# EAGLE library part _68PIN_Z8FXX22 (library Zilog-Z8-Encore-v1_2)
Z8 Encore, PLCC-68 Package
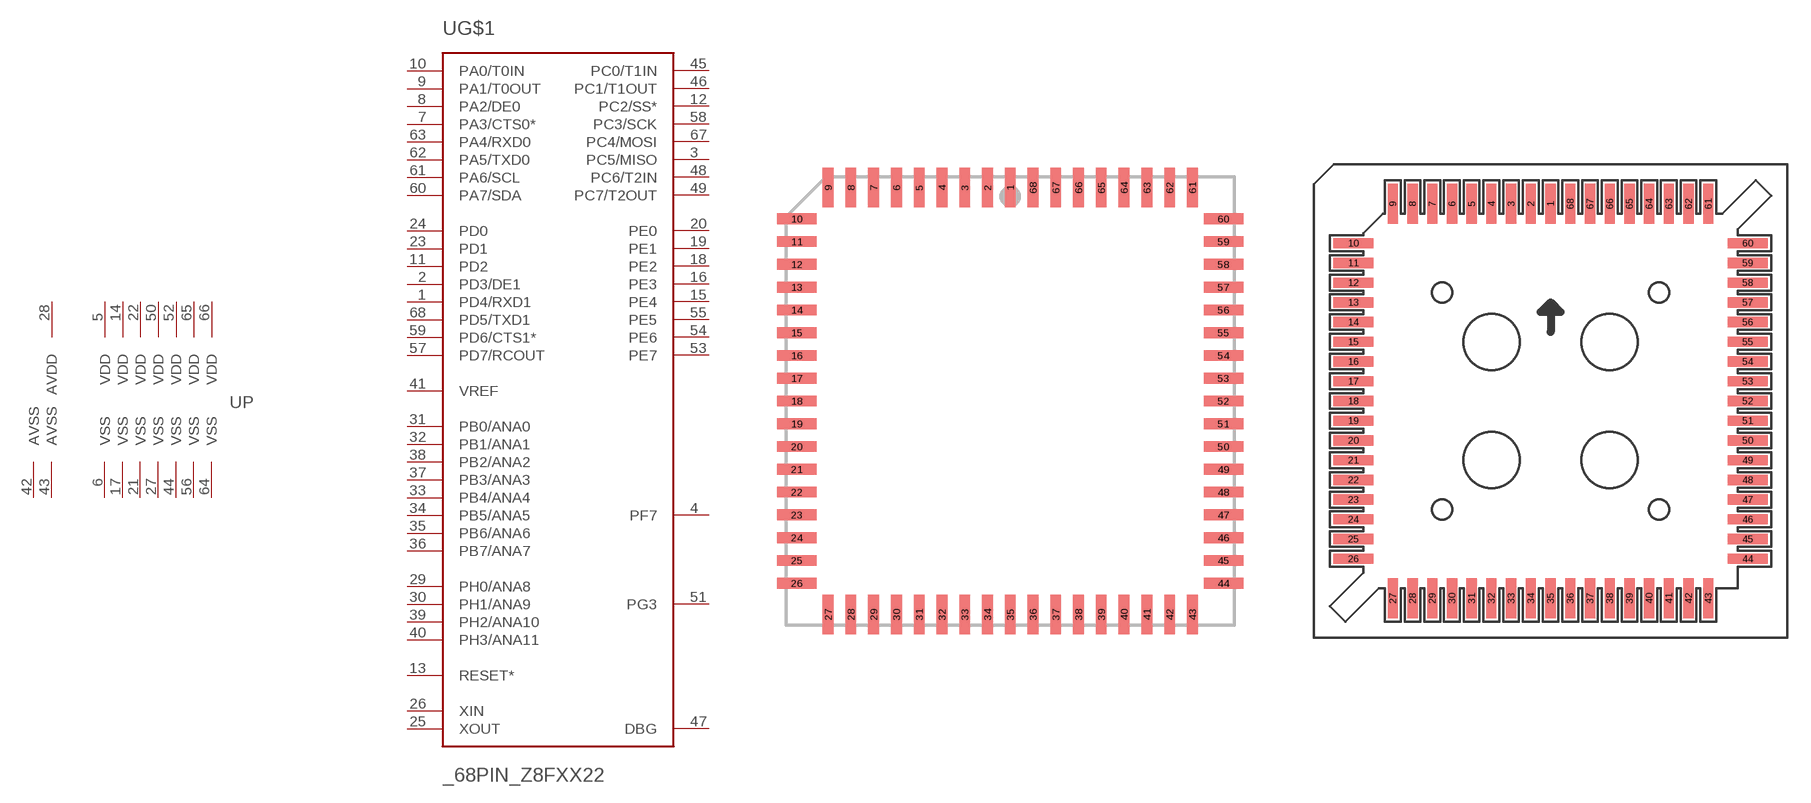
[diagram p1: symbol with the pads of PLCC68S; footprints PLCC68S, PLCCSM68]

Designator prefix U; gates G$1=Z8FXX22 P=PWR_68-PIN

## _68PIN_Z8FXX22VS  [PLCC68S]
1  G$1:PD4/RXD1
2  G$1:PD3/DE1
3  G$1:PC5/MISO
4  G$1:PF7
5  P:VDD  pwr
6  P:VSS  pwr
7  G$1:PA3/CTS0*
8  G$1:PA2/DE0
9  G$1:PA1/T0OUT
10  G$1:PA0/T0IN
11  G$1:PD2
12  G$1:PC2/SS*
13  G$1:RESET*  in
14  P:VDD  pwr
15  G$1:PE4
16  G$1:PE3
17  P:VSS  pwr
18  G$1:PE2
19  G$1:PE1
20  G$1:PE0
21  P:VSS  pwr
22  P:VDD  pwr
23  G$1:PD1
24  G$1:PD0
25  G$1:XOUT  out
26  G$1:XIN  in
27  P:VSS  pwr
28  P:AVDD  pwr
29  G$1:PH0/ANA8
30  G$1:PH1/ANA9
31  G$1:PB0/ANA0
32  G$1:PB1/ANA1
33  G$1:PB4/ANA4
34  G$1:PB5/ANA5
35  G$1:PB6/ANA6
36  G$1:PB7/ANA7
37  G$1:PB3/ANA3
38  G$1:PB2/ANA2
39  G$1:PH2/ANA10
40  G$1:PH3/ANA11
41  G$1:VREF  pas
42  P:AVSS  pwr
43  P:AVSS  pwr
44  P:VSS  pwr
45  G$1:PC0/T1IN
46  G$1:PC1/T1OUT
47  G$1:DBG
48  G$1:PC6/T2IN
49  G$1:PC7/T2OUT
50  P:VDD  pwr
51  G$1:PG3
52  P:VDD  pwr
53  G$1:PE7
54  G$1:PE6
55  G$1:PE5
56  P:VSS  pwr
57  G$1:PD7/RCOUT
58  G$1:PC3/SCK
59  G$1:PD6/CTS1*
60  G$1:PA7/SDA
61  G$1:PA6/SCL
62  G$1:PA5/TXD0
63  G$1:PA4/RXD0
64  P:VSS  pwr
65  P:VDD  pwr
66  P:VDD  pwr
67  G$1:PC4/MOSI
68  G$1:PD5/TXD1

## _68PIN_Z8FXX22VS-SMS  [PLCCSM68]
Pads as for PLCC68S

## _68PIN_Z8FXX22VS-THS  [PLCC-S68]
Pads as for PLCC68S

## Footprint PLCC68S (pad centres in mm)
PLCC-68
smd 0.6 x 2.2: 1 0,11.9; 2 -1.27,11.9; 3 -2.54,11.9; 4 -3.81,11.9; 5 -5.08,11.9; 6 -6.35,11.9; 7 -7.62,11.9; 8 -8.89,11.9; 9 -10.16,11.9; 27 -10.16,-11.9; 28 -8.89,-11.9; 29 -7.62,-11.9; 30 -6.35,-11.9; 31 -5.08,-11.9; 32 -3.81,-11.9; 33 -2.54,-11.9; 34 -1.27,-11.9; 35 0,-11.9; 36 1.27,-11.9; 37 2.54,-11.9; 38 3.81,-11.9; 39 5.08,-11.9; 40 6.35,-11.9; 41 7.62,-11.9; 42 8.89,-11.9; 43 10.16,-11.9; 61 10.16,11.9; 62 8.89,11.9; 63 7.62,11.9; 64 6.35,11.9; 65 5.08,11.9; 66 3.81,11.9; 67 2.54,11.9; 68 1.27,11.9
smd 2.2 x 0.6: 10 -11.9,10.16; 11 -11.9,8.89; 12 -11.9,7.62; 13 -11.9,6.35; 14 -11.9,5.08; 15 -11.9,3.81; 16 -11.9,2.54; 17 -11.9,1.27; 18 -11.9,0; 19 -11.9,-1.27; 20 -11.9,-2.54; 21 -11.9,-3.81; 22 -11.9,-5.08; 23 -11.9,-6.35; 24 -11.9,-7.62; 25 -11.9,-8.89; 26 -11.9,-10.16; 44 11.9,-10.16; 45 11.9,-8.89; 46 11.9,-7.62; 47 11.9,-6.35; 48 11.9,-5.08; 49 11.9,-3.81; 50 11.9,-2.54; 51 11.9,-1.27; 52 11.9,0; 53 11.9,1.27; 54 11.9,2.54; 55 11.9,3.81; 56 11.9,5.08; 57 11.9,6.35; 58 11.9,7.62; 59 11.9,8.89; 60 11.9,10.16

## Footprint PLCCSM68 (pad centres in mm)
PLCC-68 Surface-Mount Socket
smd 0.66 x 2.591: 1 0,12.7; 2 -1.27,12.7; 3 -2.54,12.7; 4 -3.81,12.7; 5 -5.08,12.7; 6 -6.35,12.7; 7 -7.62,12.7; 8 -8.89,12.7; 9 -10.16,12.7; 27 -10.16,-12.7; 28 -8.89,-12.7; 29 -7.62,-12.7; 30 -6.35,-12.7; 31 -5.08,-12.7; 32 -3.81,-12.7; 33 -2.54,-12.7; 34 -1.27,-12.7; 35 0,-12.7; 36 1.27,-12.7; 37 2.54,-12.7; 38 3.81,-12.7; 39 5.08,-12.7; 40 6.35,-12.7; 41 7.62,-12.7; 42 8.89,-12.7; 43 10.16,-12.7; 61 10.16,12.7; 62 8.89,12.7; 63 7.62,12.7; 64 6.35,12.7; 65 5.08,12.7; 66 3.81,12.7; 67 2.54,12.7; 68 1.27,12.7
smd 2.591 x 0.66: 10 -12.7,10.16; 11 -12.7,8.89; 12 -12.7,7.62; 13 -12.7,6.35; 14 -12.7,5.08; 15 -12.7,3.81; 16 -12.7,2.54; 17 -12.7,1.27; 18 -12.7,0; 19 -12.7,-1.27; 20 -12.7,-2.54; 21 -12.7,-3.81; 22 -12.7,-5.08; 23 -12.7,-6.35; 24 -12.7,-7.62; 25 -12.7,-8.89; 26 -12.7,-10.16; 44 12.7,-10.16; 45 12.7,-8.89; 46 12.7,-7.62; 47 12.7,-6.35; 48 12.7,-5.08; 49 12.7,-3.81; 50 12.7,-2.54; 51 12.7,-1.27; 52 12.7,0; 53 12.7,1.27; 54 12.7,2.54; 55 12.7,3.81; 56 12.7,5.08; 57 12.7,6.35; 58 12.7,7.62; 59 12.7,8.89; 60 12.7,10.16

## Footprint PLCC-S68 (pad centres in mm)
PLCC-68 Thru-Hole Socket
drill 0.813 octagon: 1 0,12.7; 2 0,10.16; 3 -2.54,12.7; 4 -2.54,10.16; 5 -5.08,12.7; 6 -5.08,10.16; 7 -7.62,12.7; 8 -7.62,10.16; 9 -10.16,12.7; 10 -12.7,10.16; 11 -10.16,10.16; 12 -12.7,7.62; 13 -10.16,7.62; 14 -12.7,5.08; 15 -10.16,5.08; 16 -12.7,2.54; 17 -10.16,2.54; 18 -12.7,0; 19 -10.16,0; 20 -12.7,-2.54; 21 -10.16,-2.54; 22 -12.7,-5.08; 23 -10.16,-5.08; 24 -12.7,-7.62; 25 -10.16,-7.62; 26 -12.7,-10.16; 27 -10.16,-12.7; 28 -10.16,-10.16; 29 -7.62,-12.7; 30 -7.62,-10.16; 31 -5.08,-12.7; 32 -5.08,-10.16; 33 -2.54,-12.7; 34 -2.54,-10.16; 35 0,-12.7; 36 0,-10.16; 37 2.54,-12.7; 38 2.54,-10.16; 39 5.08,-12.7; 40 5.08,-10.16; 41 7.62,-12.7; 42 7.62,-10.16; 43 10.16,-12.7; 44 12.7,-10.16; 45 10.16,-10.16; 46 12.7,-7.62; 47 10.16,-7.62; 48 12.7,-5.08; 49 10.16,-5.08; 50 12.7,-2.54; 51 10.16,-2.54; 52 12.7,0; 53 10.16,0; 54 12.7,2.54; 55 10.16,2.54; 56 12.7,5.08; 57 10.16,5.08; 58 12.7,7.62; 59 10.16,7.62; 60 12.7,10.16; 61 10.16,12.7; 62 10.16,10.16; 63 7.62,12.7; 64 7.62,10.16; 65 5.08,12.7; 66 5.08,10.16; 67 2.54,12.7; 68 2.54,10.16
